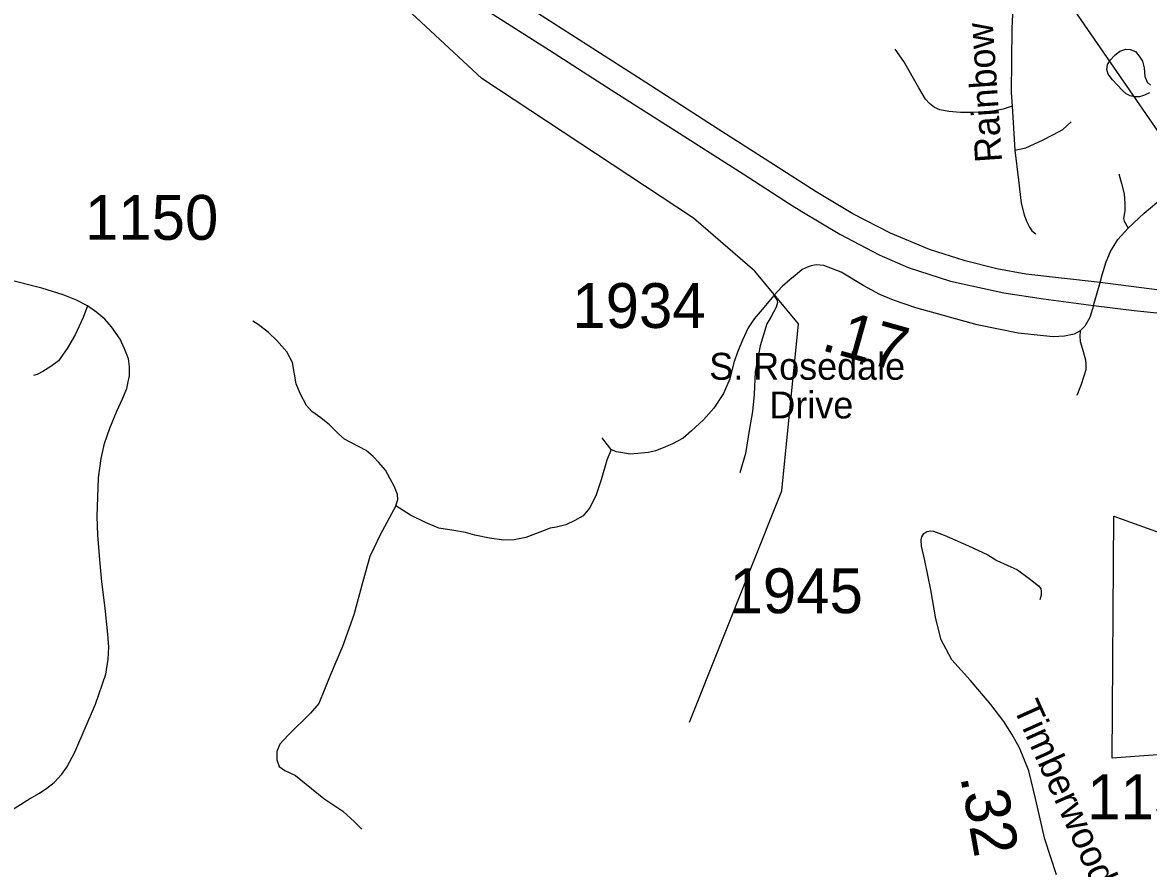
# Model space of a CAD drawing. Extents: x 1159738 to 1321356, y 736314 to 882035.
# Drawn here: x 1244144 to 1247285, y 781448 to 783806 of the extents above; entities that cross this region are included whole.
import ezdxf

# ---------------------------------------------------------------- set-up
doc = ezdxf.new("R2010")
doc.units = 0
for name, color, linetype in [('Exist Boundary Political City Limit New', 7, 'Continuous'), ('Exist Hydrographic Creek Single Shore', 7, 'Continuous'), ('Exist Road Non-System Type 51', 7, 'Continuous'), ('Exist Road Secondary Mileage Hundredths English Label', 7, 'Continuous'), ('Exist Road Secondary Type 51 Attributed', 7, 'Continuous'), ('Exist Road Secondary Type 51 Divided Attributed', 7, 'Continuous'), ('Exist Road Secondary Type 51 Label', 7, 'Continuous'), ('Exist Road Secondary Type 51 Number Label', 7, 'Continuous'), ('Exist Utilities Electrical Transmission Line', 7, 'Continuous'), ('Map Preparation Boundary City Limit Buffer Line', 7, 'Continuous')]:
    doc.layers.add(name, color=color, linetype=linetype)

msp = doc.modelspace()

# ---------------------------------------------------------------- linework, layer by layer
at = {"layer": 'Exist Boundary Political City Limit New'}
msp.add_lwpolyline([(1247626.9, 781787.6), (1247183.7, 781755.3), (1247188.3, 782430.3), (1247410.3, 782350.3)], dxfattribs=at)
at = {"layer": 'Exist Hydrographic Creek Single Shore'}
for points in [[(1246187, 783112.4), (1246016.1, 783260.2), (1245425, 783649.5), (1245230, 783830.7), (1245123, 783885.7), (1244744.5, 784127.7), (1244068.1, 784644.8), (1243717.3, 784846.8), (1243591.7, 784917.1), (1243493.7, 784983.2)], [(1246004.1, 781855.5), (1246262.1, 782500.3), (1246308.1, 782965.5), (1246187, 783112.4)]]:
    msp.add_lwpolyline(points, dxfattribs=at)
at = {"layer": 'Exist Road Non-System Type 51'}
for points in [[(1246904.4, 783572.2), (1246879.3, 783564.1), (1246845, 783557.8), (1246829.7, 783556.4), (1246789.8, 783555), (1246760.4, 783555), (1246728.2, 783557.8), (1246702.4, 783562), (1246687.7, 783569), (1246673.7, 783580.2), (1246662.5, 783592.1), (1246644.3, 783623.6), (1246602.3, 783697.1), (1246577.9, 783731.4)], [(1247287.2, 783609.5), (1247273.9, 783603.2), (1247259.2, 783599), (1247245.2, 783599), (1247233.3, 783601.8), (1247222.2, 783606.7), (1247211, 783617.2), (1247184.4, 783645.9), (1247171.8, 783662), (1247168.3, 783674.6), (1247170.4, 783688.6), (1247178.8, 783701.9), (1247190, 783713.8), (1247204.7, 783725.7), (1247221.5, 783731.3), (1247233.3, 783730.6), (1247248, 783725), (1247258.5, 783712.4), (1247267.6, 783697.7), (1247272.5, 783679.5), (1247274.6, 783655.7), (1247280.9, 783639.6), (1247290.7, 783631.2)], [(1246912.1, 783449.6), (1246942.2, 783456.6), (1246989, 783477.6), (1247019.8, 783493.7), (1247045.7, 783507.7), (1247068.8, 783528.6)], [(1247202.1, 783384), (1247209.1, 783356.7), (1247216.8, 783328), (1247218.9, 783301.4), (1247218.9, 783281.1), (1247214.7, 783259.4), (1247216.8, 783252.4), (1247228.3, 783232.8)], [(1246319.1, 783117.6), (1246304.5, 783105.6), (1246284.3, 783088.6), (1246263.4, 783069.6), (1246240, 783044.9)], [(1246240, 783044.9), (1246207.4, 783006.3), (1246185.2, 782979.6), (1246168.2, 782954.7), (1246152.6, 782920.1), (1246140.1, 782891.4), (1246128.4, 782858.1), (1246116.6, 782813), (1246099.8, 782772), (1246072.3, 782730.9), (1246043.6, 782698.2), (1246009.7, 782667.5), (1245986.9, 782647.5), (1245957.5, 782631.2), (1245931.4, 782620.1), (1245909.9, 782612.2), (1245890.3, 782607), (1245860.3, 782604.4), (1245838.7, 782603.1), (1245812.6, 782607), (1245800.5, 782609.2), (1245786.1, 782615.8)], [(1246240, 783044.9), (1246248.5, 783033.1), (1246250.4, 783025.3), (1246245.9, 783012.2), (1246231.5, 782984.8), (1246219.8, 782965.8), (1246202.1, 782904.4), (1246187.8, 782832.1), (1246184.5, 782768.7), (1246180, 782721.7), (1246172.1, 782674), (1246160.4, 782604.4), (1246145.4, 782550.2)], [(1244325.3, 783016), (1244313.6, 782983.4), (1244291.6, 782935), (1244269, 782896.8), (1244244.8, 782862.6), (1244223.6, 782846.7), (1244201.4, 782832.7), (1244185.1, 782824.8), (1244174.9, 782822.1)], [(1245185.8, 782458.4), (1245191.2, 782476.7), (1245190.6, 782490.4), (1245181.4, 782511.3), (1245156.6, 782558.3), (1245138.3, 782579.9), (1245122.7, 782596.2), (1245102.4, 782613.2), (1245042.5, 782644.9), (1245026.2, 782658), (1245000.1, 782684.8), (1244976.6, 782703.7), (1244951.1, 782722), (1244936.1, 782738.4), (1244918.6, 782772.1), (1244907.5, 782798.9), (1244897.1, 782858.3), (1244881.4, 782887.7), (1244854, 782919.1), (1244830.5, 782942), (1244801.9, 782964.5), (1244786.9, 782973.6)], [(1247094.2, 782946.2), (1247093.1, 782931.4), (1247094.2, 782916.7), (1247100.3, 782894.9), (1247108.9, 782865.9), (1247110, 782853.5), (1247109.7, 782837.7), (1247097.3, 782796.7), (1247084.5, 782765.8)], [(1245786.1, 782615.8), (1245771.7, 782633.4), (1245761.3, 782648.4)], [(1245786.1, 782615.8), (1245774.4, 782585.7), (1245758, 782530.9), (1245743, 782486.4), (1245726, 782452.5), (1245708.4, 782430.9), (1245684.9, 782417.8), (1245660.1, 782406.1), (1245634, 782398.9), (1245615.7, 782396.3), (1245594.2, 782388.4), (1245547.8, 782370.8), (1245515.2, 782363.6), (1245487.1, 782363), (1245446.7, 782368.8), (1245405.5, 782376.7), (1245379.7, 782384.5), (1245347, 782389.8), (1245305.9, 782396.3), (1245268.7, 782412), (1245226.9, 782432.9), (1245185.8, 782458.4)], [(1245185.8, 782458.4), (1245141.6, 782377.5), (1245124, 782340.9), (1245112.9, 782317.4), (1245093.9, 782247.5), (1245068.6, 782154.5), (1245036.6, 782066.3), (1245002, 781985.9), (1244970.7, 781907.9), (1244948, 781880.6), (1244885.3, 781819.9), (1244861.8, 781794.4), (1244854, 781773.5), (1244854, 781750.6), (1244860.5, 781732.3), (1244876.2, 781720.6), (1244905.5, 781707.2), (1244935.5, 781683.1), (1244984.5, 781642.6), (1245038, 781607.3), (1245070, 781577.9), (1245090.9, 781557)], [(1246714.4, 782376.5), (1246782.9, 782347), (1246836.2, 782322.3), (1246861.4, 782306.3), (1246919.8, 782280), (1246955.6, 782253.5), (1246977.8, 782235.4), (1246984, 782228.1), (1246985.6, 782220), (1246985.8, 782209.5), (1246981.2, 782196.6)]]:
    msp.add_lwpolyline(points, dxfattribs=at)
at = {"layer": 'Exist Road Secondary Type 51 Attributed'}
for points in [[(1246907.3, 783868.8), (1246903.5, 783789.3), (1246902, 783610.3), (1246904.4, 783572.2), (1246912.1, 783449.6), (1246922.4, 783366.3), (1246929.5, 783302.4), (1246937.9, 783269.5), (1246944.1, 783252), (1246953.1, 783235.4), (1246959.7, 783225.5), (1246970.6, 783216.5)], [(1247150.2, 783081.1), (1247155.5, 783102.5), (1247166.8, 783138.9), (1247178.4, 783167.1), (1247199.4, 783201), (1247228.3, 783232.8), (1247272.3, 783274.1), (1247307.5, 783304.1), (1247332.7, 783327.4), (1247376.5, 783365.6), (1247410.8, 783388.9), (1247443.8, 783408.2)], [(1247131.3, 783017.5), (1247120.9, 782983.5), (1247107.4, 782959), (1247094.2, 782946.2), (1247077.4, 782937.3), (1247050.7, 782931.7), (1247019.1, 782929.8), (1246921, 782940.4), (1246806.5, 782963.3), (1246635.6, 783010.7), (1246573.9, 783032.3), (1246535.5, 783047.3), (1246490.4, 783072.2), (1246427.4, 783109.7), (1246379.6, 783128.5), (1246358.2, 783130.4), (1246344.3, 783127.4), (1246335.7, 783124.8), (1246319.1, 783117.6)], [(1244091.2, 781596.1), (1244163.7, 781642), (1244191.7, 781657.9), (1244212.5, 781671.5), (1244232.9, 781687.9), (1244253.6, 781710.4), (1244268.3, 781730.4), (1244290.6, 781772.4), (1244347.6, 781905.6), (1244377.1, 781989.2), (1244383.5, 782031), (1244385.4, 782065), (1244382.7, 782101), (1244375.2, 782173.8), (1244365.7, 782246.7), (1244359.7, 782307.8), (1244354, 782377.8), (1244352.5, 782428.9), (1244356.3, 782536.4), (1244363.5, 782590.3), (1244373.3, 782632.2), (1244387.6, 782675.4), (1244407.3, 782722.6), (1244423.1, 782757.3), (1244434.9, 782785.3), (1244439.4, 782804.5), (1244442.8, 782820.7), (1244443.1, 782845.7), (1244439.7, 782868), (1244429.2, 782896.6), (1244416.7, 782923.4), (1244392.1, 782957.4), (1244373.6, 782978.6), (1244351.7, 782997.8), (1244325.3, 783016), (1244294.7, 783031.8), (1244258.1, 783046.9), (1244198, 783065.1), (1244099, 783090.3)], [(1247131.3, 783017.5), (1247150.2, 783081.1)], [(1247028.3, 781429.7), (1246996, 781529.7), (1246969.5, 781643.1), (1246950.5, 781720), (1246924.5, 781784), (1246903.5, 781822.2), (1246881.2, 781858), (1246845.1, 781904.6), (1246787.9, 781972), (1246736.6, 782029.5), (1246720.2, 782058.7), (1246706.4, 782085.2), (1246691.6, 782143.8), (1246677.3, 782224.9), (1246660.9, 782305.9), (1246651.9, 782346.7), (1246651.1, 782363.8), (1246652.4, 782372.5), (1246658, 782381.4), (1246666.4, 782387.5), (1246677.8, 782389), (1246685.2, 782388), (1246714.4, 782376.5)]]:
    msp.add_lwpolyline(points, dxfattribs=at)
at = {"layer": 'Exist Road Secondary Type 51 Divided Attributed'}
for points in [[(1244008, 784754.3), (1244234.6, 784609.6), (1244432, 784483.7), (1244571.7, 784393.3), (1244677.2, 784327), (1244806.1, 784244.7), (1244899.4, 784185.4), (1245018.9, 784109.4), (1245211.4, 783985.8), (1245410.9, 783857.8), (1245614.3, 783728.4), (1245786.5, 783618.5), (1245947, 783516.4), (1246154.2, 783383.7), (1246283.9, 783300.6), (1246317.7, 783279), (1246423.4, 783215.5), (1246533.6, 783158.1), (1246614.6, 783123.3), (1246732.7, 783085), (1246881.5, 783052), (1246991.4, 783035.4), (1247131.3, 783017.5)], [(1247150.2, 783081.1), (1246942.7, 783104.7), (1246861.4, 783119.4), (1246773.7, 783141.7), (1246673.6, 783173.2), (1246564.7, 783218.9), (1246459.8, 783272.3), (1246358.2, 783334), (1246216, 783424.6), (1246084.9, 783508.1), (1245882.9, 783638.2), (1245580.8, 783832), (1245433.5, 783925.4), (1245143.8, 784110), (1244950.1, 784234.7), (1244816.2, 784320.2), (1244673.7, 784409.7), (1244545.9, 784491.3), (1244401.9, 784585.4), (1244307.9, 784644.5), (1244230.3, 784691.8), (1244124.9, 784763.1)], [(1248210.5, 782972.5), (1248206.7, 782972.9), (1248086, 782985.3), (1247894.6, 783004.9), (1247774.9, 783017.3), (1247677.7, 783025.6), (1247503.9, 783041.1), (1247315.6, 783059.7), (1247150.2, 783081.1)], [(1247131.3, 783017.5), (1247244.9, 783003), (1247334.6, 782994), (1247548.1, 782968.7), (1247762.5, 782948.9), (1247926.7, 782932.5), (1248127.4, 782913.8), (1248188.4, 782906.8)]]:
    msp.add_lwpolyline(points, dxfattribs=at)
at = {"layer": 'Exist Utilities Electrical Transmission Line'}
msp.add_lwpolyline([(1245414.7, 786458.9), (1245655.3, 785949.5), (1245917.9, 785424.2), (1246149, 784983), (1246359.1, 784678.3), (1246905.4, 784090), (1247576.7, 783117), (1248027.1, 782618.2), (1248633.2, 782382.1), (1248916, 781887.4), (1248978, 781502.2), (1249135.7, 781236.5), (1249364.5, 780949.5), (1249705.2, 780536.3)], dxfattribs=at)
at = {"layer": 'Map Preparation Boundary City Limit Buffer Line'}
msp.add_lwpolyline([(1247626.9, 781787.6), (1247183.7, 781755.3), (1247188.3, 782430.3), (1247410.3, 782350.3)], dxfattribs=at)

# ---------------------------------------------------------------- texts
at = {"layer": 'Exist Road Secondary Mileage Hundredths English Label'}
for s, rotation, p in [('.17', 344.3465, (1246368.4, 782893.6)), ('.32', 280.3077, (1246759.4, 781703.6))]:
    msp.add_text(s, height=125, rotation=rotation, dxfattribs=at).set_placement(p)
at = {"layer": 'Exist Road Secondary Type 51 Label'}
for s, rotation, p in [('Rainbow', 93.8897, (1246876.6, 783418.1)), ('Timberwood Dr', 294.0982, (1246906.3, 781896.5))]:
    msp.add_text(s, height=75, rotation=rotation, dxfattribs=at).set_placement(p)
for s, p in [('S. Rosedale', (1246059.6, 782810.1)), ('Drive', (1246227.4, 782702.3))]:
    msp.add_text(s, height=75, dxfattribs=at).set_placement(p)
at = {"layer": 'Exist Road Secondary Type 51 Number Label'}
for s, p in [('1150', (1244318.6, 783200.1)), ('1934', (1245677.8, 782954.4)), ('1945', (1246116.2, 782159.4)), ('1153', (1247113.5, 781585.2))]:
    msp.add_text(s, height=125, dxfattribs=at).set_placement(p)

doc.saveas('drawing.dxf')
